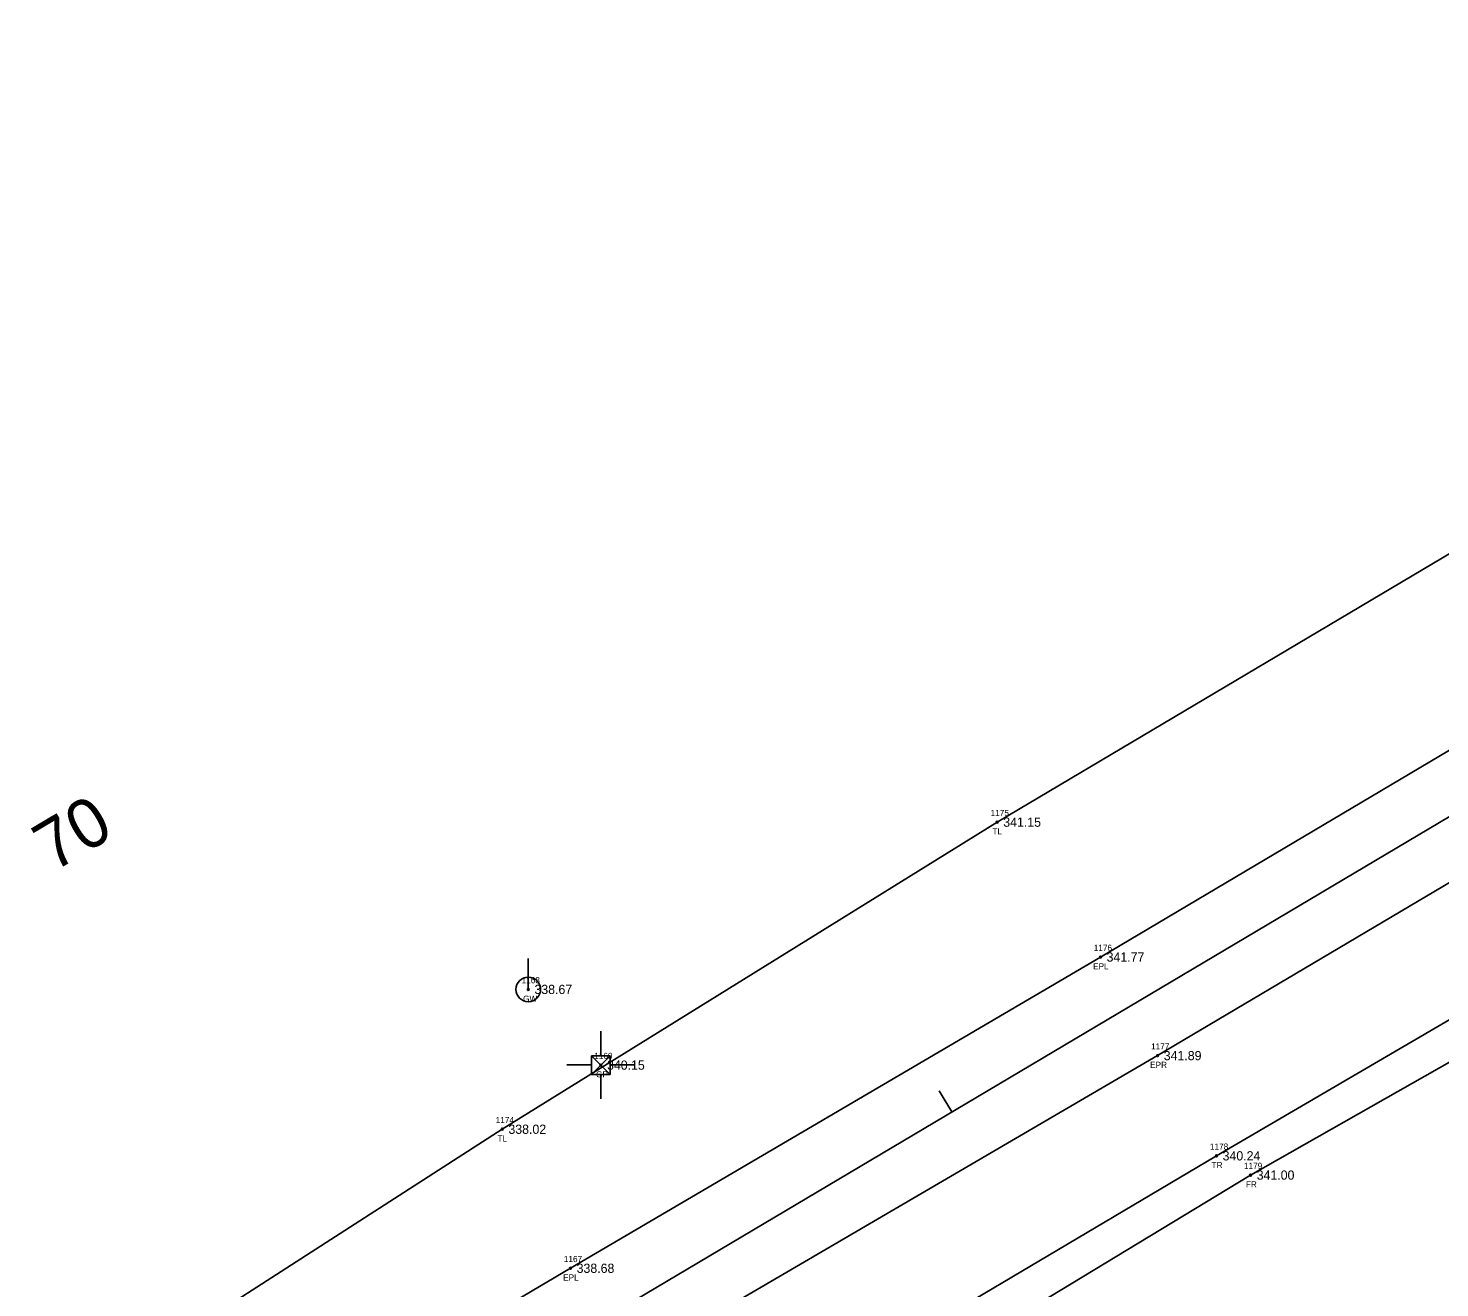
# Model space of a CAD drawing. Extents: x 2231119 to 2232595, y 1035731 to 1037094.
# Drawn here: x 2231847.5 to 2232076.9, y 1036666.5 to 1036871.1 of the extents above; entities that cross this region are included whole.
import ezdxf

# ---------------------------------------------------------------- set-up
doc = ezdxf.new("R2010")
doc.units = 0
for name, color, linetype in [('RD_EX_Fence_Other', 7, 'Continuous'), ('RD_EX_Fence_Other_txCode', 7, 'Continuous'), ('RD_EX_Road', 7, 'Continuous'), ('RD_EX_Road_txCode', 7, 'Continuous'), ('RD_EX_TX_Fence_Other_ELEV', 7, 'Continuous'), ('RD_EX_TX_Road_ELEV', 7, 'Continuous'), ('RD_EX_TX_UT_ELEV', 7, 'Continuous'), ('RD_EX_TX_VEG_ELEV', 7, 'Continuous'), ('RD_EX_UT', 7, 'Continuous'), ('RD_EX_UT_txCode', 7, 'Continuous'), ('RD_EX_VEG', 7, 'Continuous'), ('RD_EX_VEG_txCode', 7, 'Continuous'), ('RD_HC_Cl', 7, 'Continuous'), ('RD_HC_Data_Tic', 7, 'Continuous'), ('RD_HC_TX_Sta50', 7, 'Continuous'), ('RD_SMD_Locator', 7, 'Continuous')]:
    doc.layers.add(name, color=color, linetype=linetype)

msp = doc.modelspace()

# ---------------------------------------------------------------- linework, layer by layer
at = {"layer": 'RD_EX_Fence_Other'}
msp.add_lwpolyline([(2231742.82, 1036485.51), (2231730.99, 1036494.96), (2231789.88, 1036531.02), (2231876.81, 1036583.89), (2231964.37, 1036635.23), (2232046.18, 1036684.79), (2232133.57, 1036734.4), (2232210.6, 1036793.49), (2232301.78, 1036835.03)], dxfattribs=at)
at = {"layer": 'RD_EX_Road'}
for points in [[(2231606.1, 1036462.92), (2231601.27, 1036470.82), (2231681.58, 1036519.84), (2231764.99, 1036568.78), (2231851.5, 1036619.95), (2231935.62, 1036669.65), (2232021.78, 1036720.22), (2232106.75, 1036770.57), (2232190.54, 1036819.2), (2232275.92, 1036870.27)], [(2231606.1, 1036462.92), (2231610.57, 1036455.36), (2231692.09, 1036503.24), (2231706.07, 1036512.59), (2231777.1, 1036553.27), (2231861.39, 1036604.65), (2231946.39, 1036654.77), (2232031.07, 1036704.2), (2232117.06, 1036755.16), (2232199.91, 1036803.8), (2232286.7, 1036855.36)]]:
    msp.add_lwpolyline(points, dxfattribs=at)
at = {"layer": 'RD_EX_UT'}
for p, q in [((2231928.76, 1036714.96), (2231928.76, 1036719.96)), ((2231940.56, 1036704.16), (2231940.56, 1036708.16)), ((2231939.04, 1036702.71), (2231935.04, 1036702.71)), ((2231942.06, 1036704.16), (2231939.06, 1036701.16)), ((2231939.06, 1036704.16), (2231942.06, 1036701.16)), ((2231942.06, 1036704.16), (2231939.06, 1036704.16)), ((2231939.06, 1036704.16), (2231939.06, 1036701.16)), ((2231942.06, 1036701.16), (2231942.06, 1036704.16)), ((2231942.08, 1036702.73), (2231946.09, 1036702.73)), ((2231939.06, 1036701.16), (2231942.06, 1036701.16)), ((2231940.56, 1036701.16), (2231940.56, 1036697.16))]:
    msp.add_line(p, q, dxfattribs=at)
msp.add_circle((2231928.76, 1036714.96), 2, dxfattribs=at)
at = {"layer": 'RD_EX_VEG'}
for points in [[(2231598.25, 1036478.35), (2231674.54, 1036527.95), (2231759.25, 1036584.63), (2231839.99, 1036637.88), (2231924.53, 1036692.24), (2232004.98, 1036742.14), (2232090.99, 1036793.16), (2232172.16, 1036843), (2232262.27, 1036890.61)], [(2231753.59, 1036474.98), (2231730.55, 1036496.34), (2231788.45, 1036533.87), (2231871.45, 1036588.79), (2231958.94, 1036639.51), (2232040.64, 1036687.92), (2232130.59, 1036740.48), (2232213.07, 1036784.39), (2232299.54, 1036835.55)]]:
    msp.add_lwpolyline(points, dxfattribs=at)
at = {"layer": 'RD_HC_Cl'}
msp.add_line((2231548.98, 1036428.87), (2232281.06, 1036863.23), dxfattribs=at)
at = {"layer": 'RD_HC_Data_Tic'}
msp.add_line((2231997.6, 1036695.05), (2231995.56, 1036698.49), dxfattribs=at)
at = {"layer": 'RD_SMD_Locator'}
for centre in [(2232004.98, 1036742.14), (2232021.78, 1036720.22), (2231928.76, 1036714.96), (2231940.56, 1036702.66), (2232031.07, 1036704.2), (2231924.53, 1036692.24), (2232040.64, 1036687.92), (2232046.18, 1036684.79), (2231935.62, 1036669.65)]:
    msp.add_circle(centre, 0.15, dxfattribs=at)

# ---------------------------------------------------------------- texts
at = {"layer": 'RD_EX_Fence_Other_txCode'}
for s, p in [('1179', (2232045.11, 1036685.79)), ('FR', (2232045.42, 1036682.79))]:
    msp.add_text(s, height=1, dxfattribs=at).set_placement(p)
at = {"layer": 'RD_EX_Road_txCode'}
for s, p in [('1176', (2232020.69, 1036721.22)), ('EPL', (2232020.58, 1036718.22)), ('1177', (2232030.01, 1036705.2)), ('EPR', (2232029.85, 1036702.2)), ('1167', (2231934.54, 1036670.65)), ('EPL', (2231934.42, 1036667.65))]:
    msp.add_text(s, height=1, dxfattribs=at).set_placement(p)
at = {"layer": 'RD_EX_TX_Fence_Other_ELEV'}
msp.add_text('341.00', height=1.5, dxfattribs=at).set_placement((2232047.18, 1036684.04))
at = {"layer": 'RD_EX_TX_Road_ELEV'}
for s, p in [('341.77', (2232022.78, 1036719.47)), ('341.89', (2232032.07, 1036703.45)), ('338.68', (2231936.62, 1036668.9))]:
    msp.add_text(s, height=1.5, dxfattribs=at).set_placement(p)
at = {"layer": 'RD_EX_TX_UT_ELEV'}
for s, p in [('338.67', (2231929.76, 1036714.21)), ('340.15', (2231941.56, 1036701.91))]:
    msp.add_text(s, height=1.5, dxfattribs=at).set_placement(p)
at = {"layer": 'RD_EX_TX_VEG_ELEV'}
for s, p in [('341.15', (2232005.98, 1036741.39)), ('338.02', (2231925.53, 1036691.49)), ('340.24', (2232041.64, 1036687.17))]:
    msp.add_text(s, height=1.5, dxfattribs=at).set_placement(p)
at = {"layer": 'RD_EX_UT_txCode'}
for s, p in [('1168', (2231927.67, 1036715.96)), ('GW', (2231927.91, 1036712.96)), ('1169', (2231939.48, 1036703.66)), ('GP', (2231939.78, 1036700.66))]:
    msp.add_text(s, height=1, dxfattribs=at).set_placement(p)
at = {"layer": 'RD_EX_VEG_txCode'}
for s, p in [('1175', (2232003.92, 1036743.14)), ('TL', (2232004.21, 1036740.14)), ('1174', (2231923.46, 1036693.24)), ('TL', (2231923.75, 1036690.24)), ('1178', (2232039.58, 1036688.92)), ('TR', (2232039.85, 1036685.92))]:
    msp.add_text(s, height=1, dxfattribs=at).set_placement(p)
at = {"layer": 'RD_HC_TX_Sta50'}
msp.add_text('70', height=8, rotation=30.682, dxfattribs=at).set_placement((2231851.5, 1036733.95))

doc.saveas('drawing.dxf')
